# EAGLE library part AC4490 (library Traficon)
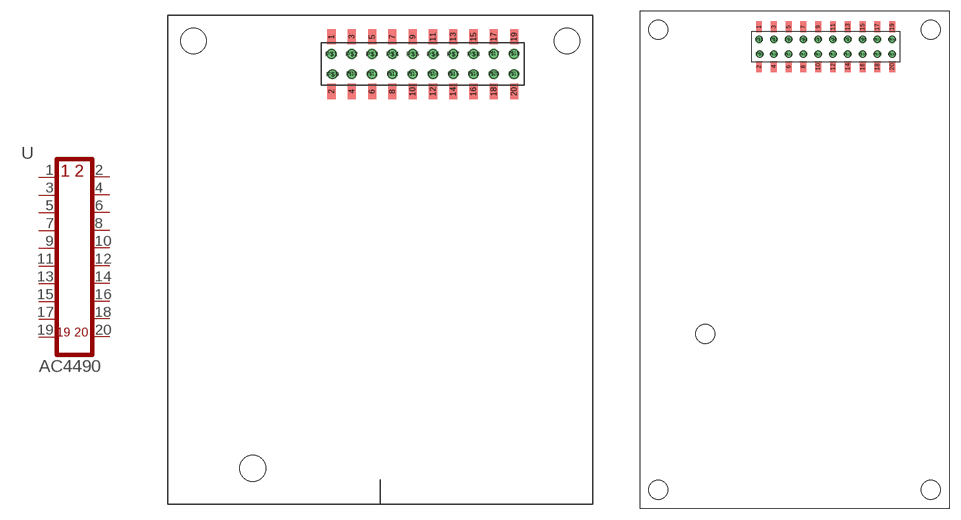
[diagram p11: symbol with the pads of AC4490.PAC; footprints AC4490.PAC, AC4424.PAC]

Designator prefix -

## AC4490  [AC4490.PAC]
1  1  pas
2  2  pas
3  3  pas
4  4  pas
5  5  pas
6  6  pas
7  7  pas
8  8  pas
9  9  pas
10  10  pas
11  11  pas
12  12  pas
13  13  pas
14  14  pas
15  15  pas
16  16  pas
17  17  pas
18  18  pas
19  19  pas
20  20  pas

## AC4490AC4424  [AC4424.PAC]
Pads as for AC4490.PAC

## Footprint AC4490.PAC (pad centres in mm)
smd 0.8 x 1.5: 1 -9,2.7; 2 -9,-2.7; 3 -7,2.7; 4 -7,-2.7; 5 -5,2.7; 6 -5,-2.7; 7 -3,2.7; 8 -3,-2.7; 9 -1,2.7; 10 -1,-2.7; 11 1,2.7; 12 1,-2.7; 13 3,2.7; 14 3,-2.7; 15 5,2.7; 16 5,-2.7; 17 7,2.7; 18 7,-2.7; 19 9,2.7; 20 9,-2.7
drill 0.406 pad 1.016 round: P$1 -9,1; P$2 -7,1; P$3 -5,1; P$4 -3,1; P$5 -1,1; P$6 1,1; P$7 3,1; P$8 5,1; P$9 -8.9,-1; P$10 -7,-1; P$11 -5,-1; P$12 -3,-1; P$13 -1,-1; P$14 1,-1; P$15 3,-1; P$16 5,-1; P$17 7,1; P$18 9,1; P$19 9,-1; P$20 7,-1
hole 0.813 at -9,1
hole 0.813 at -7,1
hole 0.813 at -5,1
hole 0.813 at -3,1
hole 0.813 at -1,1
hole 0.813 at -1,-1
hole 0.813 at -3,-1
hole 0.813 at -5,-1
hole 0.813 at -7,-1
hole 0.813 at -8.9,-1
hole 0.813 at 1,1
hole 0.813 at 3,1
hole 0.813 at 5,1
hole 0.813 at 7,1
hole 0.813 at 9,1
hole 0.813 at 9,-1
hole 0.813 at 7,-1
hole 0.813 at 5,-1
hole 0.813 at 3,-1
hole 0.813 at 1,-1
hole 2.54 at 14.224,2.286
hole 2.54 at -22.606,2.286
hole 2.54 at -16.764,-39.878

## Footprint AC4424.PAC (pad centres in mm)
smd 0.8 x 1.5: 1 -9,2.7; 2 -9,-2.7; 3 -7,2.7; 4 -7,-2.7; 5 -5,2.7; 6 -5,-2.7; 7 -3,2.7; 8 -3,-2.7; 9 -1,2.7; 10 -1,-2.7; 11 1,2.7; 12 1,-2.7; 13 3,2.7; 14 3,-2.7; 15 5,2.7; 16 5,-2.7; 17 7,2.7; 18 7,-2.7; 19 9,2.7; 20 9,-2.7
drill 0.406 pad 1.016 round: P$1 -9,1; P$2 -7,1; P$3 -5,1; P$4 -3,1; P$5 -1,1; P$6 1,1; P$7 3,1; P$8 5,1; P$9 -8.9,-1; P$10 -7,-1; P$11 -5,-1; P$12 -3,-1; P$13 -1,-1; P$14 1,-1; P$15 3,-1; P$16 5,-1; P$17 7,1; P$18 9,1; P$19 9,-1; P$20 7,-1
hole 0.813 at -9,1
hole 0.813 at -7,1
hole 0.813 at -5,1
hole 0.813 at -3,1
hole 0.813 at -1,1
hole 0.813 at -1,-1
hole 0.813 at -3,-1
hole 0.813 at -5,-1
hole 0.813 at -7,-1
hole 0.813 at -8.9,-1
hole 0.813 at 1,1
hole 0.813 at 3,1
hole 0.813 at 5,1
hole 0.813 at 7,1
hole 0.813 at 9,1
hole 0.813 at 9,-1
hole 0.813 at 7,-1
hole 0.813 at 5,-1
hole 0.813 at 3,-1
hole 0.813 at 1,-1
hole 2.54 at 14.224,2.286
hole 2.54 at -22.606,2.286
hole 2.54 at -16.256,-38.862
hole 2.54 at 14.224,-59.944
hole 2.54 at -22.606,-59.944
